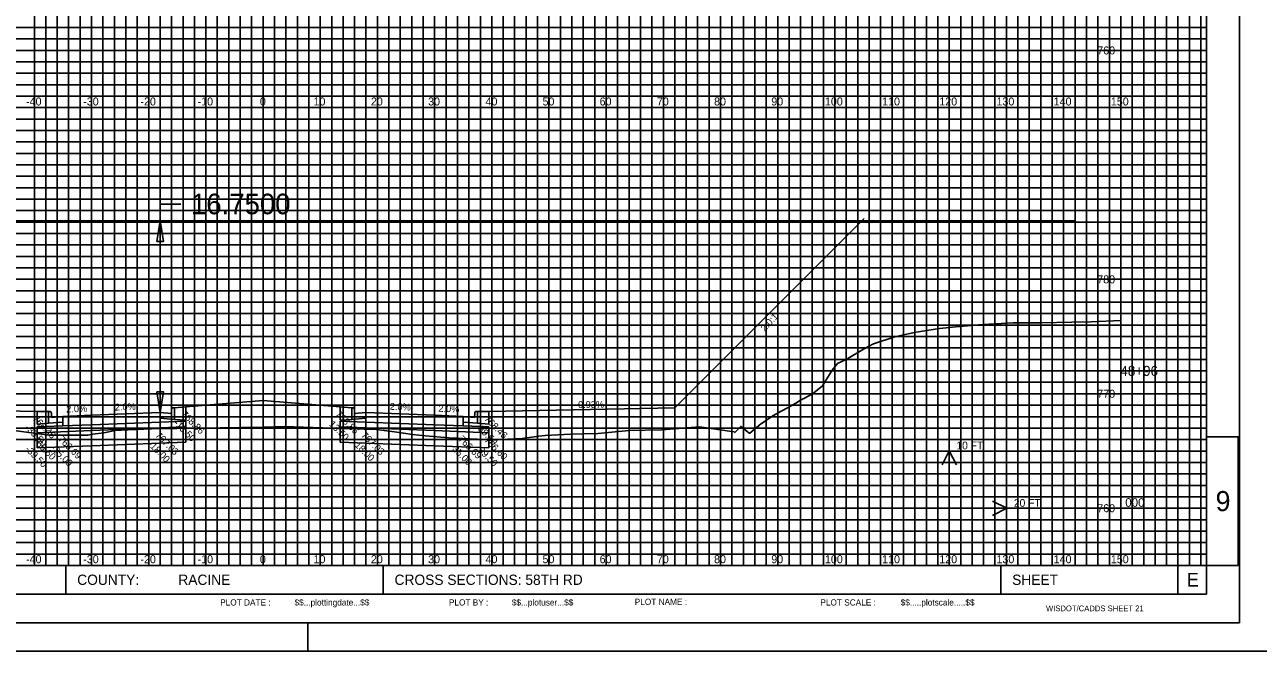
# Model space of a CAD drawing. Extents: x 578243 to 601557, y 174899 to 175559.
# Drawn here: x 600318.2 to 600533.9, y 175338.8 to 175448.3 of the extents above; entities that cross this region are included whole.
import ezdxf

# ---------------------------------------------------------------- set-up
doc = ezdxf.new("R2010")
doc.units = 0
for name, color, linetype in [('E_PROF_Grid', 7, 'Continuous'), ('E_PROF_GridMin', 7, 'Continuous'), ('P_CRDR_Label', 7, 'Continuous'), ('P_CRDR_Link', 7, 'Continuous'), ('P_E_XS_Ground', 7, 'Continuous'), ('P_RW_SlopeIntercepts', 7, 'Continuous'), ('P_XS_Text', 7, 'Continuous'), ('PLT_Sheet_Border', 7, 'Continuous'), ('PLT_Sheet_Info', 7, 'Continuous')]:
    doc.layers.add(name, color=color, linetype=linetype)

msp = doc.modelspace()

# ---------------------------------------------------------------- linework, layer by layer
at = {"layer": 'E_PROF_Grid'}
for p, q in [((600319.84, 175353.8), (600319.84, 175548.8)), ((600329.84, 175353.8), (600329.84, 175548.8)), ((600339.84, 175353.8), (600339.84, 175548.8)), ((600349.84, 175353.8), (600349.84, 175548.8)), ((600359.84, 175353.8), (600359.84, 175548.8)), ((600369.84, 175353.8), (600369.84, 175548.8)), ((600379.84, 175353.8), (600379.84, 175548.8)), ((600389.84, 175353.8), (600389.84, 175548.8)), ((600399.84, 175353.8), (600399.84, 175548.8)), ((600409.84, 175353.8), (600409.84, 175548.8)), ((600419.84, 175353.8), (600419.84, 175548.8)), ((600429.84, 175353.8), (600429.84, 175548.8)), ((600439.84, 175353.8), (600439.84, 175548.8)), ((600449.84, 175353.8), (600449.84, 175548.8)), ((600459.84, 175353.8), (600459.84, 175548.8)), ((600469.84, 175353.8), (600469.84, 175548.8)), ((600479.84, 175353.8), (600479.84, 175548.8)), ((600489.84, 175353.8), (600489.84, 175548.8)), ((600499.84, 175353.8), (600499.84, 175548.8)), ((600509.84, 175353.8), (600509.84, 175548.8)), ((600519.84, 175353.8), (600519.84, 175548.8)), ((600209.84, 175443.8), (600524.84, 175443.8)), ((600209.84, 175433.8), (600524.84, 175433.8)), ((600209.84, 175423.8), (600524.84, 175423.8)), ((600209.84, 175413.8), (600524.84, 175413.8)), ((600209.84, 175403.8), (600524.84, 175403.8)), ((600209.84, 175393.8), (600524.84, 175393.8)), ((600209.84, 175383.8), (600524.84, 175383.8)), ((600209.84, 175373.8), (600524.84, 175373.8)), ((600209.84, 175363.8), (600524.84, 175363.8))]:
    msp.add_line(p, q, dxfattribs=at)
at = {"layer": 'E_PROF_GridMin'}
for p, q in [((600321.84, 175353.8), (600321.84, 175548.8)), ((600323.84, 175353.8), (600323.84, 175548.8)), ((600325.84, 175353.8), (600325.84, 175548.8)), ((600327.84, 175353.8), (600327.84, 175548.8)), ((600331.84, 175353.8), (600331.84, 175548.8)), ((600333.84, 175353.8), (600333.84, 175548.8)), ((600335.84, 175353.8), (600335.84, 175548.8)), ((600337.84, 175353.8), (600337.84, 175548.8)), ((600341.84, 175353.8), (600341.84, 175548.8)), ((600343.84, 175353.8), (600343.84, 175548.8)), ((600345.84, 175353.8), (600345.84, 175548.8)), ((600347.84, 175353.8), (600347.84, 175548.8)), ((600351.84, 175353.8), (600351.84, 175548.8)), ((600353.84, 175353.8), (600353.84, 175548.8)), ((600355.84, 175353.8), (600355.84, 175548.8)), ((600357.84, 175353.8), (600357.84, 175548.8)), ((600361.84, 175353.8), (600361.84, 175548.8)), ((600363.84, 175353.8), (600363.84, 175548.8)), ((600365.84, 175353.8), (600365.84, 175548.8)), ((600367.84, 175353.8), (600367.84, 175548.8)), ((600371.84, 175353.8), (600371.84, 175548.8)), ((600373.84, 175353.8), (600373.84, 175548.8)), ((600375.84, 175353.8), (600375.84, 175548.8)), ((600377.84, 175353.8), (600377.84, 175548.8)), ((600381.84, 175353.8), (600381.84, 175548.8)), ((600383.84, 175353.8), (600383.84, 175548.8)), ((600385.84, 175353.8), (600385.84, 175548.8)), ((600387.84, 175353.8), (600387.84, 175548.8)), ((600391.84, 175353.8), (600391.84, 175548.8)), ((600393.84, 175353.8), (600393.84, 175548.8)), ((600395.84, 175353.8), (600395.84, 175548.8)), ((600397.84, 175353.8), (600397.84, 175548.8)), ((600401.84, 175353.8), (600401.84, 175548.8)), ((600403.84, 175353.8), (600403.84, 175548.8)), ((600405.84, 175353.8), (600405.84, 175548.8)), ((600407.84, 175353.8), (600407.84, 175548.8)), ((600411.84, 175353.8), (600411.84, 175548.8)), ((600413.84, 175353.8), (600413.84, 175548.8)), ((600415.84, 175353.8), (600415.84, 175548.8)), ((600417.84, 175353.8), (600417.84, 175548.8)), ((600421.84, 175353.8), (600421.84, 175548.8)), ((600423.84, 175353.8), (600423.84, 175548.8)), ((600425.84, 175353.8), (600425.84, 175548.8)), ((600427.84, 175353.8), (600427.84, 175548.8)), ((600431.84, 175353.8), (600431.84, 175548.8)), ((600433.84, 175353.8), (600433.84, 175548.8)), ((600435.84, 175353.8), (600435.84, 175548.8)), ((600437.84, 175353.8), (600437.84, 175548.8)), ((600441.84, 175353.8), (600441.84, 175548.8)), ((600443.84, 175353.8), (600443.84, 175548.8)), ((600445.84, 175353.8), (600445.84, 175548.8)), ((600447.84, 175353.8), (600447.84, 175548.8)), ((600451.84, 175353.8), (600451.84, 175548.8)), ((600453.84, 175353.8), (600453.84, 175548.8)), ((600455.84, 175353.8), (600455.84, 175548.8)), ((600457.84, 175353.8), (600457.84, 175548.8)), ((600461.84, 175353.8), (600461.84, 175548.8)), ((600463.84, 175353.8), (600463.84, 175548.8)), ((600465.84, 175353.8), (600465.84, 175548.8)), ((600467.84, 175353.8), (600467.84, 175548.8)), ((600471.84, 175353.8), (600471.84, 175548.8)), ((600473.84, 175353.8), (600473.84, 175548.8)), ((600475.84, 175353.8), (600475.84, 175548.8)), ((600477.84, 175353.8), (600477.84, 175548.8)), ((600481.84, 175353.8), (600481.84, 175548.8)), ((600483.84, 175353.8), (600483.84, 175548.8)), ((600485.84, 175353.8), (600485.84, 175548.8)), ((600487.84, 175353.8), (600487.84, 175548.8)), ((600491.84, 175353.8), (600491.84, 175548.8)), ((600493.84, 175353.8), (600493.84, 175548.8)), ((600495.84, 175353.8), (600495.84, 175548.8)), ((600497.84, 175353.8), (600497.84, 175548.8)), ((600501.84, 175353.8), (600501.84, 175548.8)), ((600503.84, 175353.8), (600503.84, 175548.8)), ((600505.84, 175353.8), (600505.84, 175548.8)), ((600507.84, 175353.8), (600507.84, 175548.8)), ((600511.84, 175353.8), (600511.84, 175548.8)), ((600513.84, 175353.8), (600513.84, 175548.8)), ((600515.84, 175353.8), (600515.84, 175548.8)), ((600517.84, 175353.8), (600517.84, 175548.8)), ((600521.84, 175353.8), (600521.84, 175548.8)), ((600523.84, 175353.8), (600523.84, 175548.8)), ((600209.84, 175447.8), (600524.84, 175447.8)), ((600209.84, 175445.8), (600524.84, 175445.8)), ((600209.84, 175441.8), (600524.84, 175441.8)), ((600209.84, 175439.8), (600524.84, 175439.8)), ((600209.84, 175437.8), (600524.84, 175437.8)), ((600209.84, 175435.8), (600524.84, 175435.8)), ((600209.84, 175431.8), (600524.84, 175431.8)), ((600209.84, 175429.8), (600524.84, 175429.8)), ((600209.84, 175427.8), (600524.84, 175427.8)), ((600209.84, 175425.8), (600524.84, 175425.8)), ((600209.84, 175421.8), (600524.84, 175421.8)), ((600209.84, 175419.8), (600524.84, 175419.8)), ((600209.84, 175417.8), (600524.84, 175417.8)), ((600209.84, 175415.8), (600524.84, 175415.8)), ((600209.84, 175411.8), (600524.84, 175411.8)), ((600209.84, 175409.8), (600524.84, 175409.8)), ((600209.84, 175407.8), (600524.84, 175407.8)), ((600209.84, 175405.8), (600524.84, 175405.8)), ((600209.84, 175401.8), (600524.84, 175401.8)), ((600209.84, 175399.8), (600524.84, 175399.8)), ((600209.84, 175397.8), (600524.84, 175397.8)), ((600209.84, 175395.8), (600524.84, 175395.8)), ((600209.84, 175391.8), (600524.84, 175391.8)), ((600209.84, 175389.8), (600524.84, 175389.8)), ((600209.84, 175387.8), (600524.84, 175387.8)), ((600209.84, 175385.8), (600524.84, 175385.8)), ((600209.84, 175381.8), (600524.84, 175381.8)), ((600209.84, 175379.8), (600524.84, 175379.8)), ((600209.84, 175377.8), (600524.84, 175377.8)), ((600209.84, 175375.8), (600524.84, 175375.8)), ((600209.84, 175371.8), (600524.84, 175371.8)), ((600209.84, 175369.8), (600524.84, 175369.8)), ((600209.84, 175367.8), (600524.84, 175367.8)), ((600209.84, 175365.8), (600524.84, 175365.8)), ((600209.84, 175361.8), (600524.84, 175361.8)), ((600209.84, 175359.8), (600524.84, 175359.8)), ((600209.84, 175357.8), (600524.84, 175357.8)), ((600209.84, 175355.8), (600524.84, 175355.8)), ((600527.19, 175338.8), (600537.19, 175338.8))]:
    msp.add_line(p, q, dxfattribs=at)
at = {"layer": 'P_CRDR_Link'}
msp.add_line((600464.95, 175414.44), (600431.84, 175381.32), dxfattribs=at)
for points in [[(600346.34, 175381.52), (600359.84, 175382.6)], [(600346.34, 175381.52), (600359.84, 175382.6)], [(600359.84, 175382.6), (600346.34, 175381.52)], [(600359.84, 175382.6), (600373.34, 175381.52)], [(600359.84, 175382.6), (600373.34, 175381.52)], [(600373.34, 175381.52), (600359.84, 175382.6)], [(600320.34, 175380.72), (600287.84, 175381.32)], [(600320.34, 175380.72), (600287.84, 175381.32)], [(600322.34, 175380.68), (600320.34, 175380.72)], [(600320.34, 175380.72), (600320.34, 175378.48)], [(600320.34, 175380.72), (600320.34, 175378.48)], [(600320.34, 175380.72), (600320.34, 175378.48)], [(600322.66, 175380.68), (600322.34, 175380.68)], [(600322.66, 175380.68), (600322.34, 175380.68)], [(600322.34, 175380.68), (600322.34, 175378.64)], [(600322.34, 175378.64), (600322.34, 175380.68)], [(600322.74, 175380.64), (600322.66, 175380.68)], [(600322.74, 175380.64), (600322.66, 175380.68)], [(600322.8, 175380.52), (600322.74, 175380.64)], [(600322.8, 175380.52), (600322.74, 175380.64)], [(600322.83, 175380.36), (600322.8, 175380.52)], [(600322.83, 175380.36), (600322.8, 175380.52)], [(600322.84, 175379.68), (600322.83, 175380.36)], [(600322.84, 175379.68), (600322.83, 175380.36)], [(600341.84, 175380.52), (600329.84, 175380.04)], [(600341.84, 175380.52), (600341.84, 175378.86)], [(600341.84, 175380.52), (600341.84, 175378.86)], [(600341.84, 175380.52), (600341.84, 175378.86)], [(600341.84, 175380.52), (600343.84, 175380.36)], [(600341.84, 175380.52), (600343.84, 175380.36)], [(600341.84, 175379.52), (600341.84, 175380.52)], [(600343.84, 175380.36), (600343.85, 175381.04)], [(600343.84, 175380.36), (600343.85, 175381.04)], [(600343.85, 175381.04), (600343.88, 175381.2)], [(600343.85, 175381.04), (600343.88, 175381.2)], [(600343.88, 175381.2), (600343.94, 175381.32)], [(600343.88, 175381.2), (600343.94, 175381.32)], [(600343.94, 175381.32), (600344.02, 175381.36)], [(600343.94, 175381.32), (600344.02, 175381.36)], [(600344.02, 175381.36), (600344.34, 175381.36)], [(600344.02, 175381.36), (600344.34, 175381.36)], [(600344.34, 175381.36), (600346.34, 175381.52)], [(600344.34, 175381.36), (600344.34, 175379.32)], [(600344.34, 175379.32), (600344.34, 175381.36)], [(600346.34, 175381.52), (600346.34, 175379.16)], [(600346.34, 175381.52), (600346.34, 175379.16)], [(600346.34, 175381.52), (600346.34, 175379.16)], [(600346.34, 175381.52), (600346.34, 175381.52)], [(600346.34, 175381.52), (600346.34, 175381.52)], [(600346.34, 175381.52), (600346.34, 175381.52)], [(600375.34, 175381.36), (600373.34, 175381.52)], [(600373.34, 175381.52), (600373.34, 175379.16)], [(600373.34, 175381.52), (600373.34, 175379.16)], [(600373.34, 175381.52), (600373.34, 175379.16)], [(600373.34, 175381.52), (600373.34, 175381.52)], [(600373.34, 175381.52), (600373.34, 175381.52)], [(600373.34, 175381.52), (600373.34, 175381.52)], [(600375.66, 175381.36), (600375.34, 175381.36)], [(600375.66, 175381.36), (600375.34, 175381.36)], [(600375.34, 175381.36), (600375.34, 175379.32)], [(600375.34, 175379.32), (600375.34, 175381.36)], [(600375.74, 175381.32), (600375.66, 175381.36)], [(600375.74, 175381.32), (600375.66, 175381.36)], [(600375.8, 175381.2), (600375.74, 175381.32)], [(600375.8, 175381.2), (600375.74, 175381.32)], [(600375.83, 175381.04), (600375.8, 175381.2)], [(600375.83, 175381.04), (600375.8, 175381.2)], [(600375.84, 175380.36), (600375.83, 175381.04)], [(600375.84, 175380.36), (600375.83, 175381.04)], [(600377.84, 175380.52), (600375.84, 175380.36)], [(600377.84, 175380.52), (600375.84, 175380.36)], [(600377.84, 175380.52), (600389.84, 175380.04)], [(600377.84, 175380.52), (600377.84, 175378.86)], [(600377.84, 175380.52), (600377.84, 175378.86)], [(600377.84, 175380.52), (600377.84, 175378.86)], [(600377.84, 175379.52), (600377.84, 175380.52)], [(600396.84, 175379.68), (600396.85, 175380.36)], [(600396.84, 175379.68), (600396.85, 175380.36)], [(600396.85, 175380.36), (600396.88, 175380.52)], [(600396.85, 175380.36), (600396.88, 175380.52)], [(600396.88, 175380.52), (600396.94, 175380.64)], [(600396.88, 175380.52), (600396.94, 175380.64)], [(600396.94, 175380.64), (600397.02, 175380.68)], [(600396.94, 175380.64), (600397.02, 175380.68)], [(600397.02, 175380.68), (600397.34, 175380.68)], [(600397.02, 175380.68), (600397.34, 175380.68)], [(600397.34, 175380.68), (600399.34, 175380.72)], [(600397.34, 175380.68), (600397.34, 175378.64)], [(600397.34, 175378.64), (600397.34, 175380.68)], [(600399.34, 175380.72), (600431.84, 175381.32)], [(600399.34, 175380.72), (600431.84, 175381.32)], [(600399.34, 175380.72), (600399.34, 175378.48)], [(600399.34, 175380.72), (600399.34, 175378.48)], [(600399.34, 175380.72), (600399.34, 175378.48)], [(600320.34, 175378.48), (600322.34, 175378.64)], [(600324.84, 175378.18), (600320.34, 175378)], [(600320.34, 175378), (600320.34, 175377)], [(600322.34, 175378.64), (600324.84, 175378.84)], [(600322.34, 175378.64), (600324.84, 175378.84)], [(600324.84, 175379.84), (600322.84, 175379.68)], [(600324.84, 175379.84), (600322.84, 175379.68)], [(600329.84, 175380.04), (600324.84, 175379.84)], [(600324.84, 175379.84), (600324.84, 175378.18)], [(600324.84, 175378.84), (600324.84, 175379.84)], [(600329.84, 175378.38), (600324.84, 175378.18)], [(600329.84, 175380.04), (600329.84, 175378.38)], [(600329.84, 175380.04), (600329.84, 175378.38)], [(600341.84, 175378.86), (600329.84, 175378.38)], [(600329.84, 175378.38), (600329.84, 175377.38)], [(600329.84, 175378.38), (600329.84, 175377.38)], [(600344.34, 175379.32), (600341.84, 175379.52)], [(600344.34, 175379.32), (600341.84, 175379.52)], [(600346.34, 175379.04), (600341.84, 175378.86)], [(600341.84, 175378.86), (600341.84, 175377.86)], [(600341.84, 175378.86), (600341.84, 175377.86)], [(600341.84, 175378.86), (600341.84, 175377.86)], [(600346.34, 175378.04), (600341.84, 175377.86)], [(600346.34, 175379.16), (600344.34, 175379.32)], [(600346.34, 175379.04), (600346.34, 175378.04)], [(600346.34, 175378.04), (600346.34, 175375.37)], [(600373.34, 175379.16), (600375.34, 175379.32)], [(600373.34, 175379.04), (600377.84, 175378.86)], [(600373.34, 175379.04), (600373.34, 175378.04)], [(600373.34, 175378.04), (600377.84, 175377.86)], [(600373.34, 175378.04), (600373.34, 175375.37)], [(600375.34, 175379.32), (600377.84, 175379.52)], [(600375.34, 175379.32), (600377.84, 175379.52)], [(600377.84, 175378.86), (600389.84, 175378.38)], [(600377.84, 175378.86), (600377.84, 175377.86)], [(600377.84, 175378.86), (600377.84, 175377.86)], [(600377.84, 175378.86), (600377.84, 175377.86)], [(600389.84, 175380.04), (600389.84, 175378.38)], [(600389.84, 175380.04), (600394.84, 175379.84)], [(600389.84, 175380.04), (600389.84, 175378.38)], [(600389.84, 175378.38), (600389.84, 175377.38)], [(600389.84, 175378.38), (600394.84, 175378.18)], [(600389.84, 175378.38), (600389.84, 175377.38)], [(600394.84, 175379.84), (600394.84, 175378.18)], [(600394.84, 175379.84), (600396.84, 175379.68)], [(600394.84, 175379.84), (600396.84, 175379.68)], [(600394.84, 175378.84), (600394.84, 175379.84)], [(600397.34, 175378.64), (600394.84, 175378.84)], [(600397.34, 175378.64), (600394.84, 175378.84)], [(600394.84, 175378.18), (600399.34, 175378)], [(600399.34, 175378.48), (600397.34, 175378.64)], [(600399.34, 175378), (600399.34, 175377)], [(600329.84, 175377.38), (600320.34, 175377)], [(600320.34, 175377), (600320.34, 175374.33)], [(600341.84, 175377.86), (600329.84, 175377.38)], [(600329.84, 175377.38), (600329.84, 175374.71)], [(600329.84, 175377.38), (600329.84, 175374.71)], [(600341.84, 175377.86), (600341.84, 175375.19)], [(600341.84, 175377.86), (600341.84, 175375.19)], [(600341.84, 175377.86), (600341.84, 175375.19)], [(600377.84, 175377.86), (600389.84, 175377.38)], [(600377.84, 175377.86), (600377.84, 175375.19)], [(600377.84, 175377.86), (600377.84, 175375.19)], [(600377.84, 175377.86), (600377.84, 175375.19)], [(600389.84, 175377.38), (600389.84, 175374.71)], [(600389.84, 175377.38), (600399.34, 175377)], [(600389.84, 175377.38), (600389.84, 175374.71)], [(600399.34, 175377), (600399.34, 175374.33)], [(600329.84, 175374.71), (600320.34, 175374.33)], [(600341.84, 175375.19), (600329.84, 175374.71)], [(600341.84, 175375.19), (600346.34, 175375.37)], [(600377.84, 175375.19), (600373.34, 175375.37)], [(600377.84, 175375.19), (600389.84, 175374.71)], [(600389.84, 175374.71), (600399.34, 175374.33)]]:
    msp.add_lwpolyline(points, dxfattribs=at)
at = {"layer": 'P_E_XS_Ground'}
msp.add_lwpolyline([(600315.83, 175377.47), (600322.39, 175376.57), (600322.76, 175376.57), (600323.08, 175376.56), (600329.18, 175376.55), (600330.09, 175376.76), (600331.98, 175376.96), (600334, 175377.38), (600336.24, 175377.5), (600340.31, 175377.67), (600344.77, 175377.74), (600359.84, 175377.99), (600363.61, 175378.06), (600370.31, 175377.82), (600373.06, 175377.75), (600373.06, 175377.76), (600376.21, 175377.67), (600377.45, 175377.62), (600379.68, 175377.53), (600382.83, 175377.16), (600385.95, 175376.68), (600388.16, 175376.47), (600392.35, 175376.1), (600393.15, 175376.05), (600393.66, 175376.02), (600393.95, 175376.03), (600393.95, 175376.03), (600393.95, 175376.03), (600394.58, 175375.98), (600394.58, 175375.98), (600394.74, 175375.97), (600397.33, 175375.87), (600399.97, 175375.68), (600402.59, 175375.88), (600405.15, 175376.01), (600408.05, 175376.37), (600409.2, 175376.52), (600413.62, 175376.76), (600418.43, 175376.88), (600423.83, 175377.36), (600429.56, 175377.51), (600434.02, 175377.82), (600436.16, 175378.01), (600442.2, 175377.15), (600442.24, 175377.14), (600442.33, 175377.01), (600443.38, 175378.09), (600444.46, 175377.25), (600444.84, 175376.89), (600444.98, 175376.92), (600446.47, 175378.17), (600446.51, 175378.14), (600446.62, 175378.31), (600448.96, 175379.96), (600450.43, 175380.78), (600451.65, 175381.4), (600453.01, 175382.18), (600453.84, 175382.68), (600455.86, 175383.74), (600457.66, 175385.2), (600459.35, 175387.9), (600460.32, 175389.1), (600461.82, 175389.81), (600464.83, 175391.61), (600466.6, 175392.51), (600470.33, 175393.76), (600473.71, 175394.53), (600478.16, 175395.19), (600481, 175395.51), (600485.73, 175395.91), (600490.99, 175396.19), (600495.95, 175396.2), (600501.3, 175396.32), (600504.65, 175396.35), (600509.84, 175396.62)], dxfattribs=at)
at = {"layer": 'P_RW_SlopeIntercepts'}
for p, q in [((600341.84, 175416.95), (600345.44, 175416.95)), ((600341.84, 175380.52), (600341.84, 175416.95)), ((600241.84, 175414.02), (600501.84, 175414.02))]:
    msp.add_line(p, q, dxfattribs=at)
for points in [[(600341.24, 175410.42), (600342.44, 175410.42), (600341.84, 175414.02)], [(600341.24, 175384.12), (600342.44, 175384.12), (600341.84, 175380.52)]]:
    msp.add_lwpolyline(points, close=True, dxfattribs=at)
at = {"layer": 'PLT_Sheet_Border'}
for points in [[(600197.19, 175338.8), (600537.19, 175338.8), (600537.19, 175558.8), (600197.19, 175558.8)], [(600199.59, 175343.8), (600530.59, 175343.8), (600530.59, 175553.8), (600199.59, 175553.8)]]:
    msp.add_lwpolyline(points, close=True, dxfattribs=at)
at = {"layer": 'PLT_Sheet_Info'}
for p, q in [((600524.84, 175348.8), (600524.84, 175548.8)), ((600209.84, 175353.8), (600524.84, 175353.8)), ((600325.34, 175348.8), (600325.34, 175353.8)), ((600380.84, 175348.8), (600380.84, 175353.8)), ((600488.84, 175348.8), (600488.84, 175353.8)), ((600519.84, 175348.8), (600519.84, 175353.8)), ((600209.84, 175348.8), (600524.84, 175348.8)), ((600367.69, 175338.8), (600367.69, 175343.8)), ((600362.69, 175338.8), (600372.69, 175338.8))]:
    msp.add_line(p, q, dxfattribs=at)
msp.add_lwpolyline([(600524.84, 175376.3), (600530.34, 175376.3), (600530.34, 175353.8), (600524.84, 175353.8)], close=True, dxfattribs=at)
for points in [[(600479.84, 175373.84), (600478.6, 175371.36)], [(600479.84, 175363.8), (600479.84, 175373.84), (600481.08, 175371.36)], [(600489.89, 175363.8), (600487.4, 175365.04)], [(600479.84, 175363.8), (600489.89, 175363.8), (600487.4, 175362.55)]]:
    msp.add_lwpolyline(points, dxfattribs=at)

# ---------------------------------------------------------------- texts
at = {"layer": 'P_CRDR_Label'}
for s, rotation, p in [('2.0:1', 46.711, (600447.58, 175394.61)), ('0.93%', 0.4313, (600414.93, 175381.31)), ('768.46', 315, (600319.41, 175379.31)), ('2.0%', 2.2906, (600325.44, 175380.52)), ('2.0%', 2.2906, (600333.94, 175380.86)), ('768.86', 315, (600345.41, 175380.11)), ('768.86', 315, (600372.41, 175380.11)), ('2.0%', 357.7094, (600381.99, 175381.01)), ('2.0%', 357.7094, (600390.49, 175380.67)), ('768.46', 315, (600398.41, 175379.31)), ('-39.50', 315, (600318.13, 175377.74)), ('-13.50', 315, (600344.13, 175378.55)), ('13.50', 315, (600371.3, 175378.38)), ('39.50', 315, (600397.33, 175377.55)), ('766.60', 315, (600319.41, 175375.58)), ('766.69', 315, (600323.91, 175375.76)), ('767.03', 315, (600340.91, 175376.44)), ('767.03', 315, (600340.91, 175376.44)), ('767.03', 315, (600340.91, 175376.44)), ('767.03', 315, (600376.91, 175376.44)), ('767.03', 315, (600376.91, 175376.44)), ('767.03', 315, (600376.91, 175376.44)), ('766.69', 315, (600393.91, 175375.76)), ('766.60', 315, (600398.41, 175375.58)), ('-39.50', 315, (600318.14, 175374.02)), ('-35.00', 315, (600322.62, 175374.21)), ('-18.00', 315, (600339.62, 175374.9)), ('-18.00', 315, (600339.62, 175374.9)), ('-18.00', 315, (600339.62, 175374.9)), ('18.00', 315, (600375.78, 175374.73)), ('18.00', 315, (600375.78, 175374.73)), ('18.00', 315, (600375.78, 175374.73)), ('35.00', 315, (600392.82, 175374.02)), ('39.50', 315, (600397.33, 175373.82))]:
    msp.add_text(s, height=1.2, rotation=rotation, dxfattribs=at).set_placement(p)
at = {"layer": 'P_RW_SlopeIntercepts'}
msp.add_text('16.7500', height=3.6, dxfattribs=at).set_placement((600347.24, 175415.17))
at = {"layer": 'P_XS_Text'}
for s, height, p in [('760', 1.4, (600505.72, 175443.1)), ('-40', 1.4, (600318.39, 175434.18)), ('-30', 1.4, (600328.39, 175434.18)), ('-20', 1.4, (600338.39, 175434.18)), ('-10', 1.4, (600348.39, 175434.18)), ('0', 1.4, (600359.28, 175434.18)), ('0', 1.4, (600359.28, 175434.18)), ('10', 1.4, (600368.66, 175434.18)), ('20', 1.4, (600378.7, 175434.18)), ('30', 1.4, (600388.7, 175434.18)), ('40', 1.4, (600398.74, 175434.18)), ('50', 1.4, (600408.71, 175434.18)), ('60', 1.4, (600418.7, 175434.18)), ('70', 1.4, (600428.71, 175434.18)), ('80', 1.4, (600438.71, 175434.18)), ('90', 1.4, (600448.72, 175434.18)), ('100', 1.4, (600458.1, 175434.18)), ('110', 1.4, (600468.1, 175434.18)), ('120', 1.4, (600478.1, 175434.18)), ('130', 1.4, (600488.1, 175434.18)), ('140', 1.4, (600498.1, 175434.18)), ('150', 1.4, (600508.1, 175434.18)), ('780', 1.4, (600505.72, 175403.1)), ('48+96', 1.75, (600509.77, 175386.93)), ('770', 1.4, (600505.72, 175383.1)), ('760', 1.4, (600505.72, 175363.1)), ('-40', 1.4, (600318.39, 175354.19)), ('-30', 1.4, (600328.39, 175354.19)), ('-20', 1.4, (600338.39, 175354.19)), ('-10', 1.4, (600348.39, 175354.19)), ('0', 1.4, (600359.28, 175354.19)), ('0', 1.4, (600359.28, 175354.19)), ('10', 1.4, (600368.66, 175354.19)), ('20', 1.4, (600378.7, 175354.19)), ('30', 1.4, (600388.7, 175354.19)), ('40', 1.4, (600398.74, 175354.19)), ('50', 1.4, (600408.71, 175354.19)), ('60', 1.4, (600418.7, 175354.19)), ('70', 1.4, (600428.71, 175354.19)), ('80', 1.4, (600438.71, 175354.19)), ('90', 1.4, (600448.72, 175354.19)), ('100', 1.4, (600458.1, 175354.19)), ('110', 1.4, (600468.1, 175354.19)), ('120', 1.4, (600478.1, 175354.19)), ('130', 1.4, (600488.1, 175354.19)), ('140', 1.4, (600498.1, 175354.19)), ('150', 1.4, (600508.1, 175354.19))]:
    msp.add_text(s, height=height, rotation=360, dxfattribs=at).set_placement(p)
at = {"layer": 'PLT_Sheet_Info'}
for s, height, p in [('  10 FT', 1.347, (600480.09, 175374.09)), ('  20 FT', 1.347, (600490.14, 175364.05)), ('     000', 1.5, (600507.84, 175364.05)), ('9', 3.5, (600526.42, 175363.3)), ('COUNTY:', 1.8, (600327.34, 175350.4)), ('       RACINE       ', 1.8, (600340.34, 175350.4)), ('CROSS SECTIONS: 58TH RD                           ', 1.8, (600382.84, 175350.4)), ('SHEET ', 1.8, (600490.84, 175350.4)), ('E', 2.4, (600521.36, 175350.11)), ('PLOT NAME :                      ', 1.08, (600424.84, 175346.9)), ('PLOT SCALE : ', 1.08, (600457.3, 175346.8)), ('$$.....plotscale.....$$', 1.08, (600471.34, 175346.8)), ('WISDOT/CADDS SHEET 21', 1, (600496.76, 175345.8))]:
    msp.add_text(s, height=height, dxfattribs=at).set_placement(p)
for s, p in [('PLOT DATE :', (600352.34, 175346.8)), ('$$...plottingdate...$$', (600365.34, 175346.8)), ('PLOT BY :', (600392.34, 175346.8)), ('$$...plotuser...$$', (600403.34, 175346.8))]:
    msp.add_text(s, height=1.08, rotation=360, dxfattribs=at).set_placement(p)

doc.saveas('drawing.dxf')
